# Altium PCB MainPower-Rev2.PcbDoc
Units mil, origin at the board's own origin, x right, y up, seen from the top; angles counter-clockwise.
Board outline 7780 x 7780 mil, 4 copper layers (Top Layer, Internal Plane 1, Internal Plane 2, Bottom Layer); 127 components, 91 nets, 528 pads, 0 vias.
Unrouted connection lines stored in the file: 357.
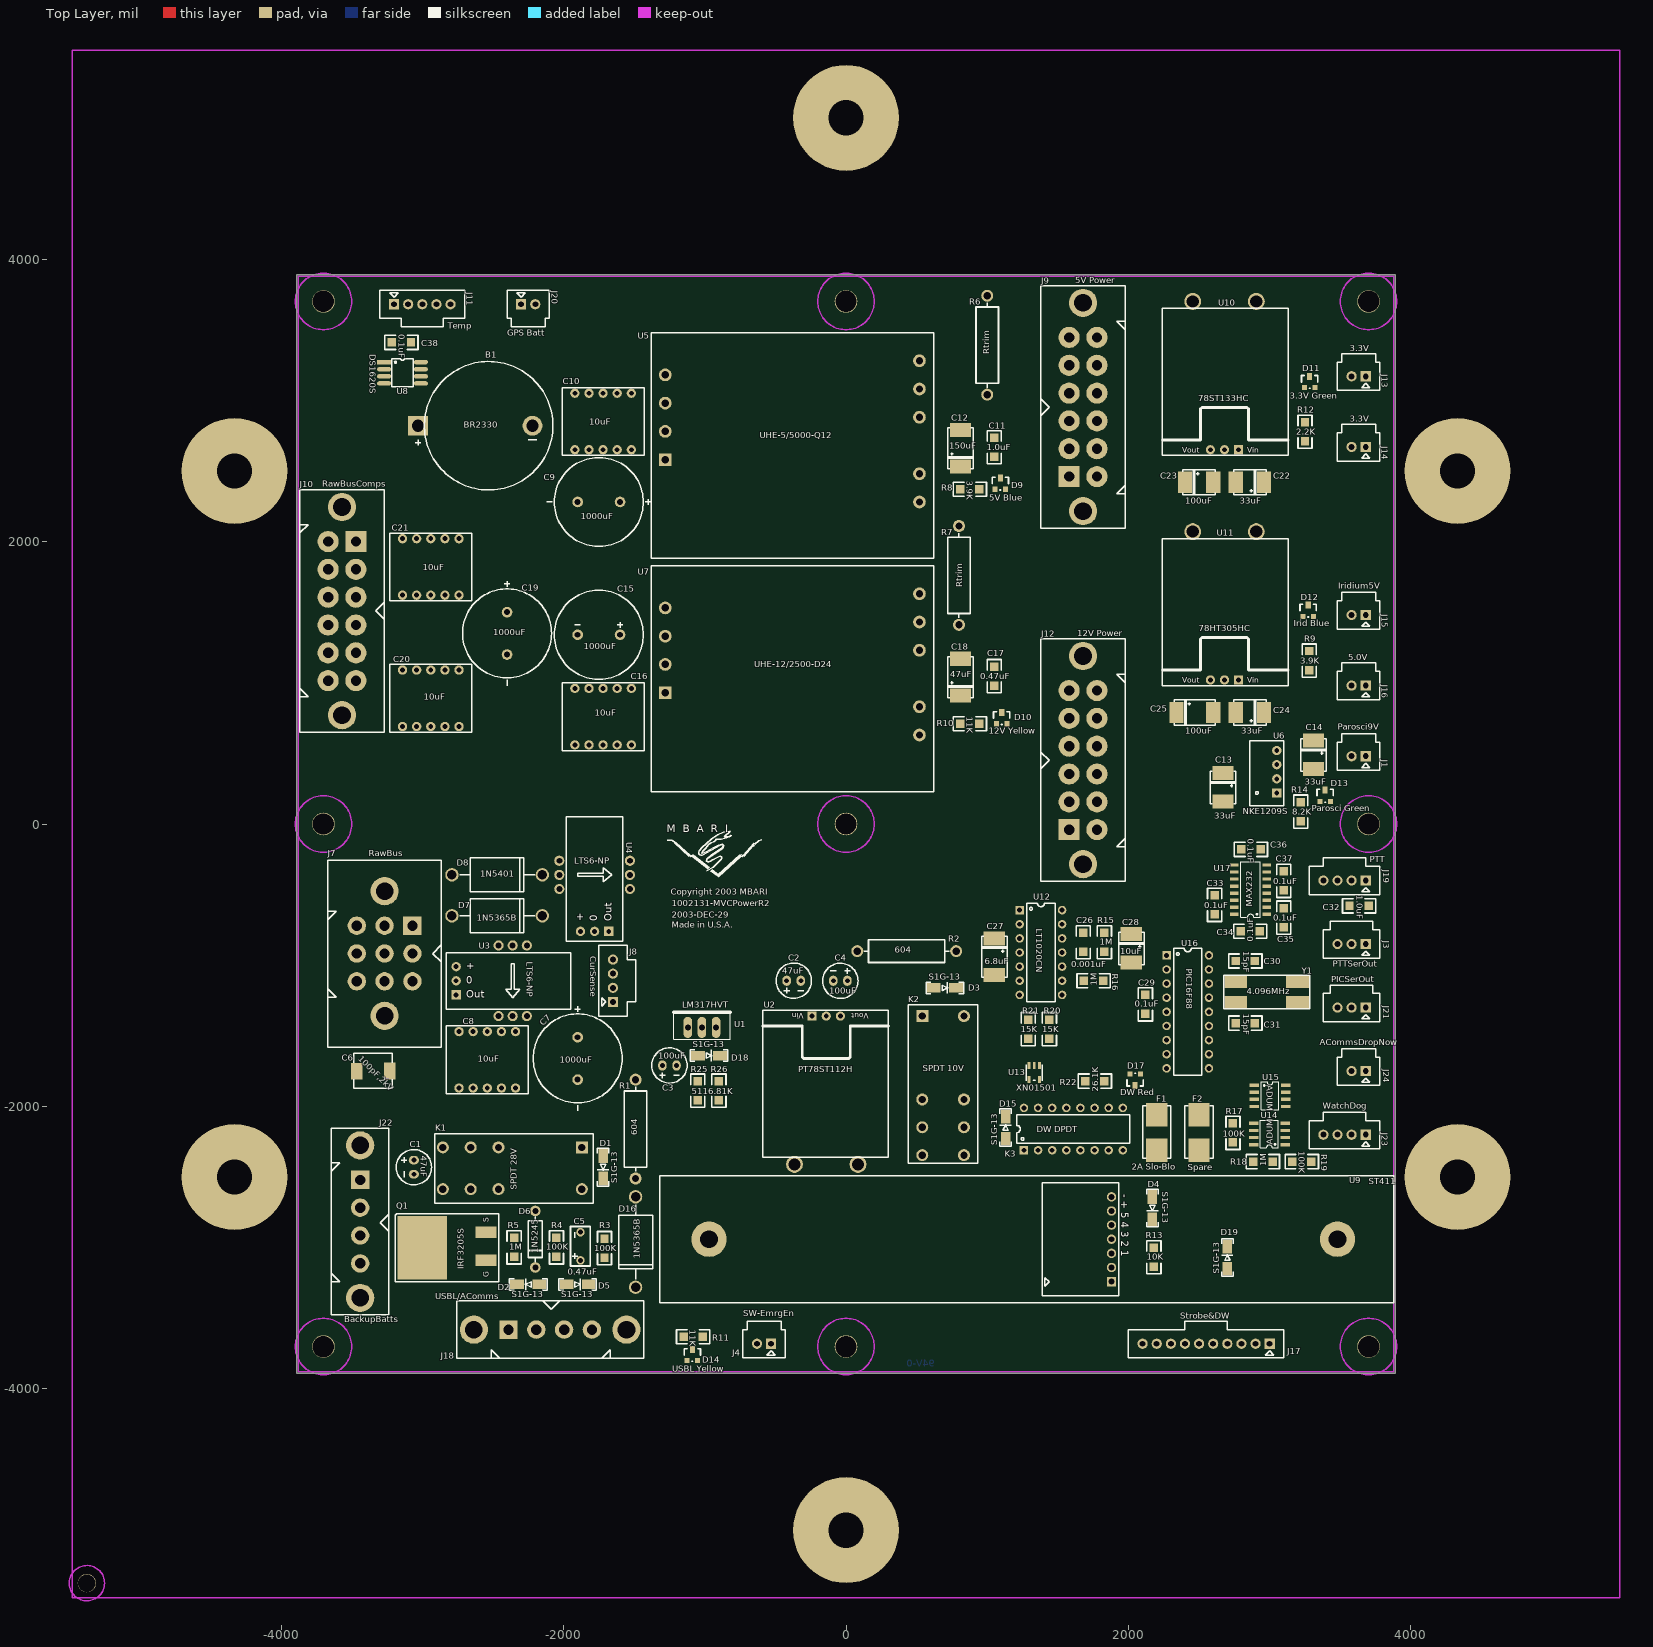
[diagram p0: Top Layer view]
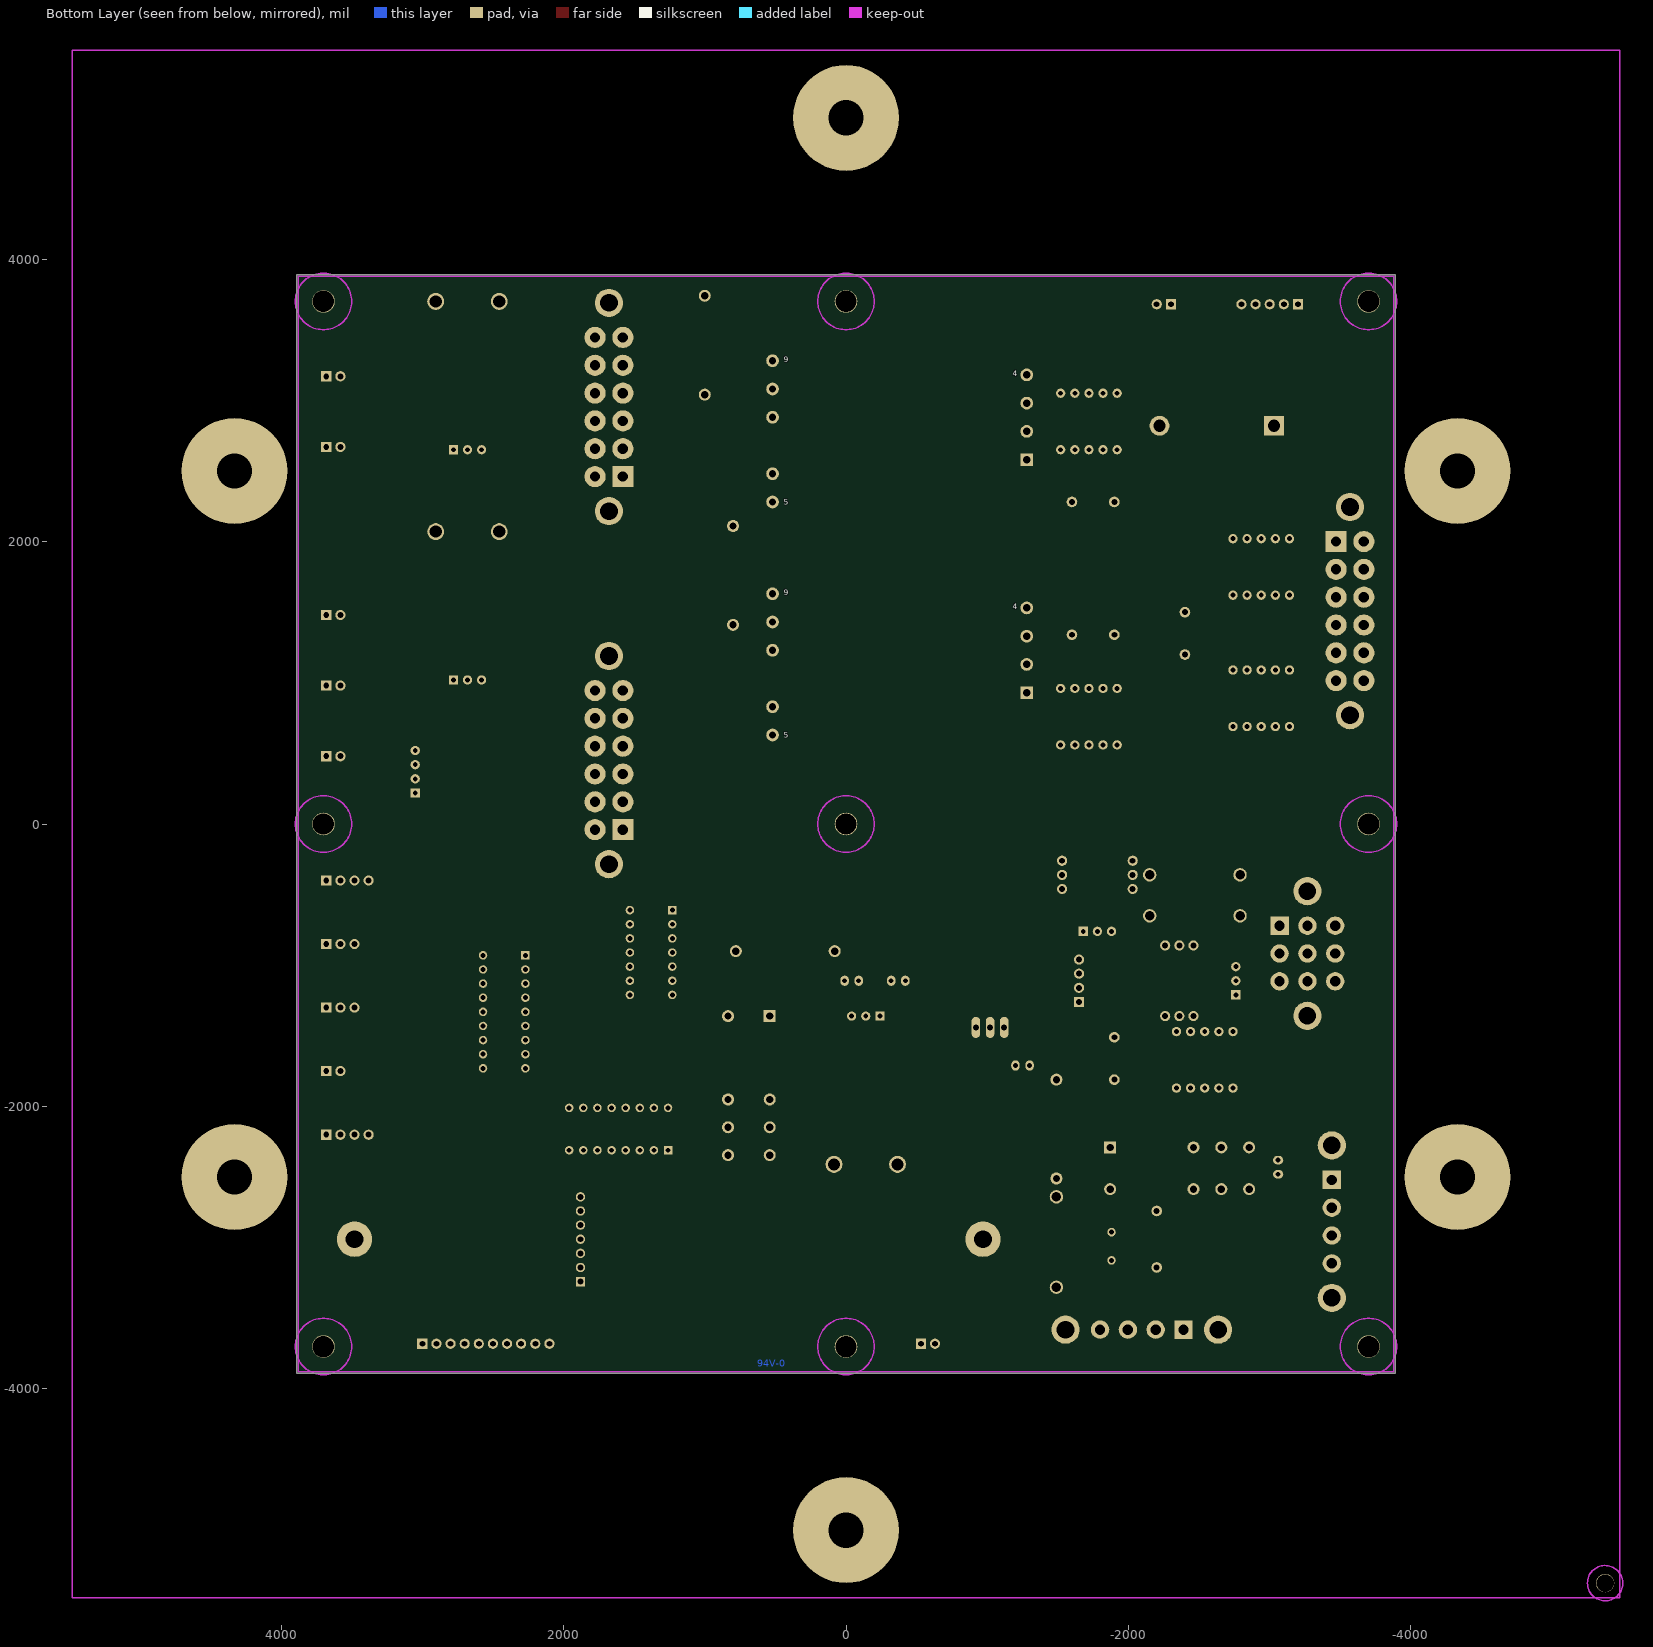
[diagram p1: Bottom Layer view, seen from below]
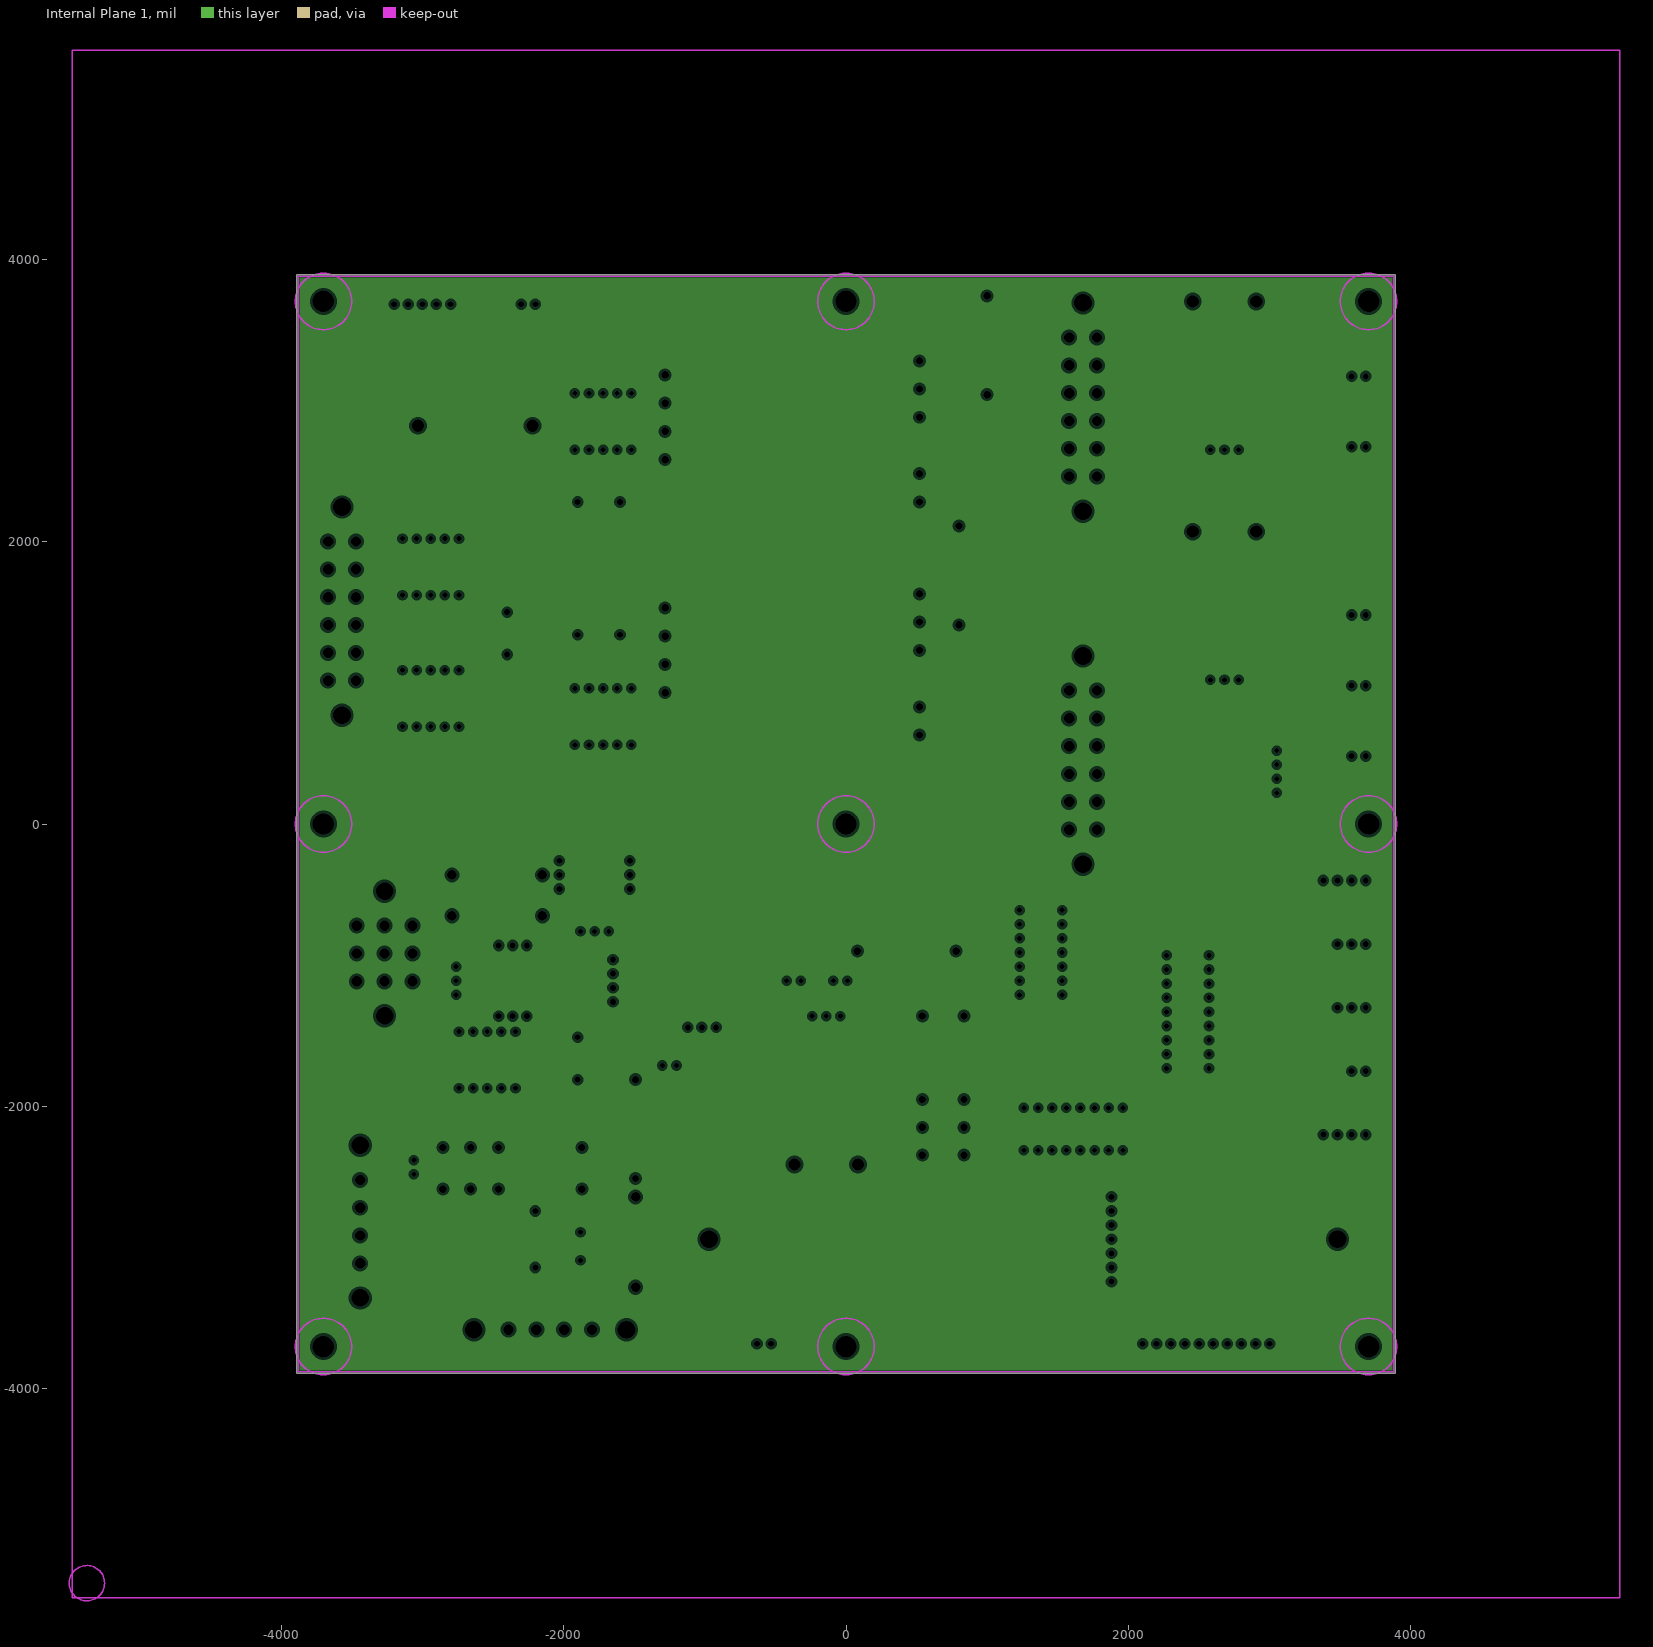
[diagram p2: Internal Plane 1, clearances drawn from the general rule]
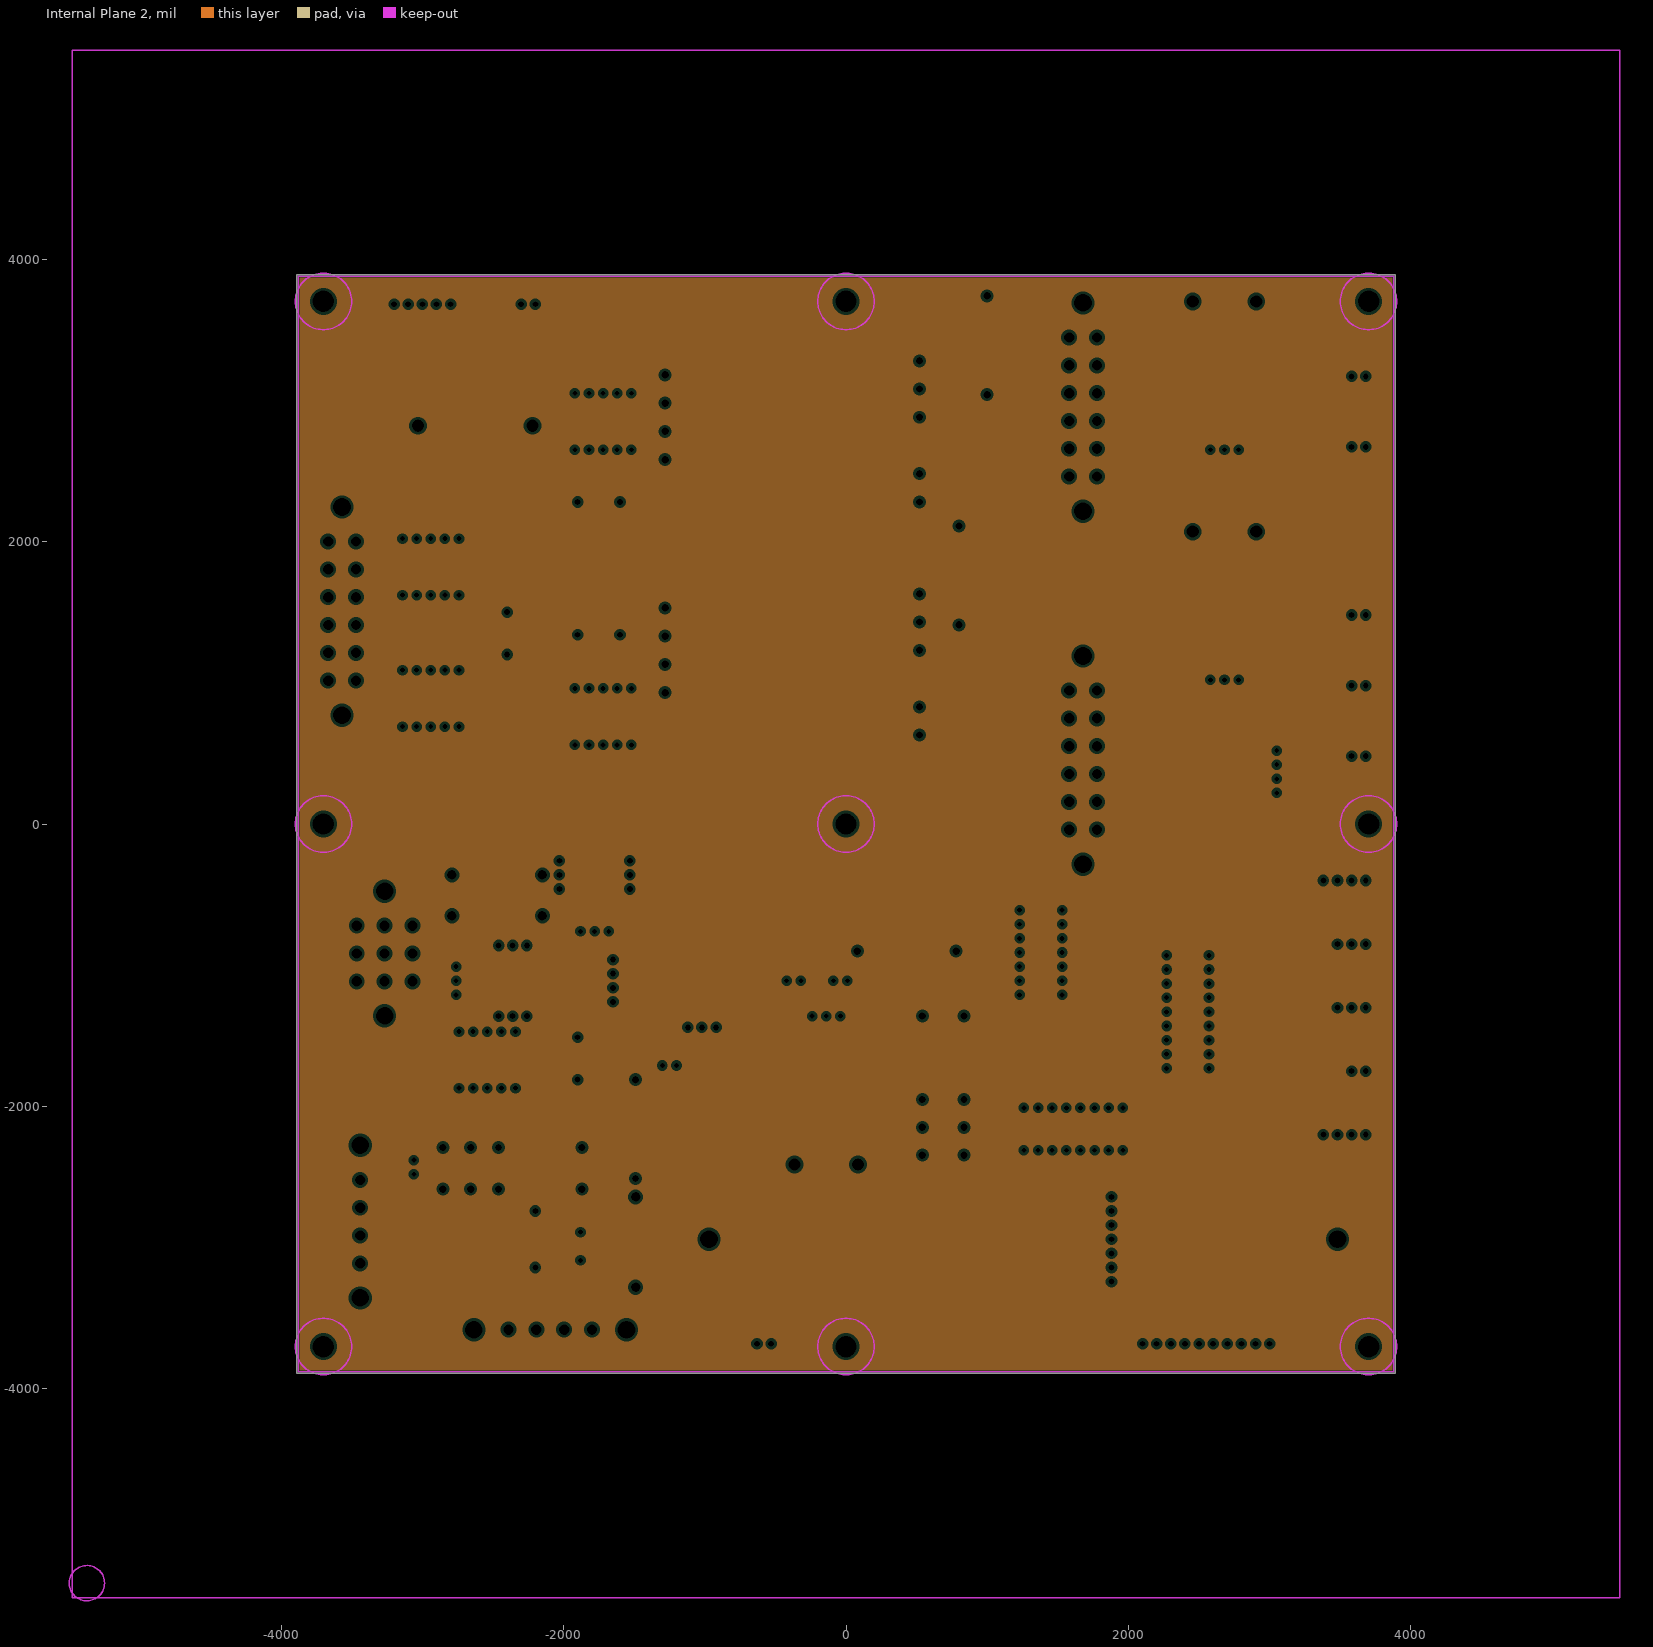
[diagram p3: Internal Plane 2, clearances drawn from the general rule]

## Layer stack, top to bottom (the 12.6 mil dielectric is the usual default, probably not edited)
Top Layer: signal copper 1.4
Dielectric: dielectric 12.6, FR-4, Dk 4.8
Internal Plane 1: plane copper 1.4
Dielectric: dielectric 12.6, FR-4, Dk 4.8
Internal Plane 2: plane copper 1.4
Dielectric: dielectric 12.6, FR-4, Dk 4.8
Bottom Layer: signal copper 1.4

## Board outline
-3890,3890 3890,3890 3890,-3890 -3890,-3890

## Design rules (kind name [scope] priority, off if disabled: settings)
Clearance powers [(InNetClass('BackupBattPower') OR InNetClass('RawPower') OR InNetClass('RegVoltage'))] p1: gap=20
Clearance [All] p2: gap=10
ComponentClearance [All] p1 off: gap=10 collisioncheckmode=0
FanoutControl Fanout_Small [(CompPinCount < 5)] p1: bgadir=Out bgaviamode=Centered fanoutstyle=Auto fanoutdirection=OutThenIn viagrid=1 // Fanout_Small (Default Rule)
FanoutControl Fanout_Default [All] p2: bgadir=Out bgaviamode=Centered fanoutstyle=Auto fanoutdirection=Alternating viagrid=1 // Fanout_Default (Default Rule)
FanoutControl Fanout_BGA [IsBGA] p4: bgadir=Out bgaviamode=Centered fanoutstyle=Auto fanoutdirection=Alternating viagrid=1 // Fanout_BGA (Default Rule)
FanoutControl Fanout_LCC [IsLCC] p5: bgadir=Out bgaviamode=Centered fanoutstyle=Auto fanoutdirection=Alternating viagrid=1 // Fanout_LCC (Default Rule)
HoleSize [All] p1: absolutevalues=TRUE maxlimit=250 minlimit=1 maxpercent=80.000 minpercent=20.000
PlaneClearance [All] p1: clearance=20
PlaneConnect [All] p1: planeconnectstyle=Relief reliefexpansion=20 reliefentries=4 reliefconductorwidth=10 reliefairgap=10
PolygonConnect [All] p1: connectstyle=Relief reliefconductorwidth=10 reliefentries=4 polygonreliefangle="90 Angle"
RoutingCorners [All] p1: cornerstyle=Round minsetback=100 maxsetback=100
RoutingLayers [All] p1: top layer=Horizontal bottom layer=Vertical
RoutingPriority raw_powers [InNetClass('RawPower')] p1: routingpriority=90
RoutingPriority regpow [InNetClass('RegVoltage')] p2: routingpriority=70
RoutingPriority battpow [InNetClass('BackupBattPower')] p3: routingpriority=80
RoutingPriority [All] p4: routingpriority=0
RoutingVias [All] p1: holewidth=35 width=52 viastyle="Through Hole" minholewidth=28 minwidth=35 maxholewidth=86 maxwidth=100
SolderMaskExpansion [All] p1: expansion=4
TestPointUsage [All] p1: valid=0 allowmultiple=FALSE
Testpoint [All] p1: side=15 testpointundercomponent=TRUE minsize=40 maxsize=100 preferedsize=60 minholesize=0 maxholesize=40 preferedholesize=32 testpointgrid=1 style=1023 order=-539222988
Width raw_power [InNetClass('RawPower')] p1: maxlimit=500 minlimit=10 preferedwidth=10 toplayer_minwidth=20 toplayer_prefwidth=50 bottomlayer_minwidth=20 bottomlayer_prefwidth=50 minimp=50.000000 maximp=50.000000 favimp=50.000000
Width backup_batt_pow [InNetClass('BackupBattPower')] p2: maxlimit=500 minlimit=10 preferedwidth=10 toplayer_minwidth=20 toplayer_prefwidth=30 bottomlayer_minwidth=20 bottomlayer_prefwidth=30 minimp=50.000000 maximp=50.000000 favimp=50.000000
Width reg_pow [InNetClass('RegVoltage')] p3: maxlimit=250 minlimit=10 preferedwidth=10 toplayer_minwidth=20 toplayer_prefwidth=30 bottomlayer_minwidth=20 bottomlayer_prefwidth=30 minimp=50.000000 maximp=50.000000 favimp=50.000000
Width [All] p4: maxlimit=500 minlimit=8 preferedwidth=12 toplayer_prefwidth=10 bottomlayer_prefwidth=10 minimp=50.000000 maximp=50.000000 favimp=50.000000
7 further rules are at their usual default settings.

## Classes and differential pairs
component class Watchdog-Rev2: C26 C27 C28 C29 C30 C31 C33 C34 C35 C36 C37 D15 D17 F1 F2 J3 J21 J25 J26 K3 R15 R16 R17 R18 R19 R20 R21 R22 R23 R24 U12 U13 U14 U15 U16 U17 Y1
component class "Parosci Iso": C13 C14 U6
component class MainPower-Rev2: B1 C19 C20 C21 C32 C38 D9 D10 D11 D12 D13 D14 D19 J1 J7 J8 J9 J10 J11 J12 J13 J14 J15 J16 J17 J18 J19 J20 J22 J23 J24 R8 R9 R10 R11 R12 R13 R14 U8 U9
component class Iridium: C24 C25 U11
component class Input-Caps-Diodes-CurrentSensing: C6 C7 C8 D7 D8 U3 U4
component class ISO12V-30W-MVC-Rev2: C15 C16 C17 C18 R7 U7
component class ISO5V-25W-MVC-Rev2: C9 C10 C11 C12 R6 U5
component class GPS: C22 C23 U10
component class BattBacked-Rev2: C1 C2 C3 C4 C5 D1 D2 D3 D4 D5 D6 D16 D18 J4 K1 K2 Q1 R1 R2 R3 R4 R5 R25 R26 U1 U2
net class BackupBattPower: BACKUP10+ BACKUP28+ DW28V DW+ DW- DWGND SW10VDC V+USBL
net class RegVoltage: 12VGND DW5V IRID5V+ MVC3.3V+ MVC5V+ MVC12V+ MVCGND PARO9V+ PARO9VGND SW10VDC V+USBL
net class RawPower: ELEC+ LOCO+ RAWBUS+ RAWBUS-

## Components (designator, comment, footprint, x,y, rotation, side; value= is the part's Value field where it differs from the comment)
B1 "BR2330" BR2330-BAT -2530,2820 r180 top
C1 "47uF" RAD0.1L_0.25D -3060,-2380 r270 top
C2 "47uF" RAD0.1L_0.25D -420,-1110 r0 top
C3 "100uF" RAD0.1L_0.25D -1300,-1710 r0 top
C4 "100uF" RAD0.1L_0.25D 10,-1110 r180 top
C5 "0.47uF" RAD0.2_POL -1880,-3090 r90 top
C6 "100pF,2kV" ECK -3470,-1730 r0 top
C7 "1000uF" RAD0.3L_0.63D -1900,-1510 r270 top
C8 "10uF" CAPSTICK-CS4-5 -2740,-1470 r0 top
C9 "1000uF" RAD0.3L_0.63D -1600,2280 r180 top
C10 "10uF" CAPSTICK-CS4-5 -1520,2650 r180 top
C11 "1.0uF" 1206 1050,2600 r90 top
C12 "150uF" 7343pol 810,2530 r90 top
C13 "33uF" 6032pol 2670,360 r270 top
C14 "33uF" 6032pol 3310,590 r270 top
C15 "1000uF" RAD0.3L_0.63D -1600,1340 r180 top
C16 "10uF" CAPSTICK-CS4-5 -1520,560 r180 top
C17 "0.47uF" 1206 1050,980 r90 top
C18 "47uF" 7343pol 810,910 r90 top
C19 "1000uF" RAD0.3L_0.63D -2400,1500 r270 top
C20 "10uF" CAPSTICK-CS4-5 -2740,690 r180 top
C21 "10uF" CAPSTICK-CS4-5 -3140,2020 r0 top
C22 "33uF" 6032pol 2960,2420 r180 top
C23 "100uF" 6032pol 2400,2420 r0 top
C24 "33uF" 6032pol 2960,790 r180 top
C25 "100uF" 7343pol 2340,790 r0 top
C26 "0.001uF" 1206 1680,-770 r270 top
C27 "6.8uF" 7343pol 1050,-810 r270 top
C28 "10uF" 6032pol 2020,-780 r270 top
C29 "0.1uF" 1206 2120,-1210 r270 top
C30 "15pF" 1206 2760,-970 r0 top
C31 "15pF" 1206 2760,-1410 r0 top
C32 "1.0uF" 1206 3700,-580 r180 top
C33 "0.1uF" 1206 2610,-640 r90 top
C34 "0.1uF" 1206 2930,-760 r180 top
C35 "0.1uF" 1206 3100,-730 r90 top
C36 "0.1uF" 1206 2800,-180 r0 top
C37 "0.1uF" 1206 3100,-470 r90 top
C38 "0.1uF" 1206 -3080,3410 r180 top
D1 "S1G-13" SMA -1720,-2430 r270 top
D2 "S1G-13" SMA -2250,-3260 r180 top
D3 "S1G-13" SMA 700,-1160 r0 top
D4 "S1G-13" SMA 2170,-2720 r270 top
D5 "S1G-13" SMA -1900,-3260 r0 top
D6 "1N5245" DIODE0.4 -2200,-2740 r270 top
D7 "1N5365B" DO-201AD -2790,-650 r0 top
D8 "1N5401" DO-201AD -2790,-360 r0 top
D9 "5V Blue" SOT-23 1130,2370 r0 top
D10 "12V Yellow" SOT-23 1140,710 r0 top
D11 "3.3V Green" SOT-23 3320,3090 r0 top
D12 "Irid Blue" SOT-23 3310,1470 r0 top
D13 "Parosci Green" SOT-23 3430,160 r0 top
D14 "USBL Yellow" SOT-23 -1050,-3800 r0 top
D15 "S1G-13" SMA 1130,-2150 r90 top
D16 "1N5365B" DO-201AD -1490,-2640 r270 top
D17 "DW Red" SOT-23 2010,-1770 r180 top
D18 "S1G-13" SMA -970,-1640 r0 top
D19 "S1G-13" SMA 2700,-3070 r90 top
F1 "2A Slo-Blo" SMF-OMNIBLOK 2200,-2310 r90 top
F2 "Spare 2A Slo-Blo" SMF-OMNIBLOK 2500,-2310 r90 top
J1 "Parosci9V" CGRID2 3680,480 r0 top
J3 "PTTSerOut" CGRID3 3680,-850 r0 top
J4 "SW-EmrgEn" CGRID2 -530,-3680 r0 top
J7 "RawBus" PLC09 -3070,-720 r270 top
J8 "CurSense" CGRID4 -1650,-1260 r270 top
J9 "5V Power" PLB12 1580,2460 r90 top
J10 "RawBusComps" PLB12 -3470,2000 r270 top
J11 "Temp" CGRID5 -3200,3680 r180 top
J12 "12V Power" PLB12 1580,-40 r90 top
J13 "3.3V" CGRID2 3680,3170 r0 top
J14 "3.3V" CGRID2 3680,2670 r0 top
J15 "Iridium5V" CGRID2 3680,1480 r0 top
J16 "5.0V" CGRID2 3680,980 r0 top
J17 "Strobe&DW" CGRID10 3000,-3680 r0 top
J18 "USBL/AComms" PLA04 -2390,-3580 r0 top
J19 "PTT" CGRID4 3680,-400 r0 top
J20 "GPS Batt" CGRID2 -2300,3680 r180 top
J21 "PICSerOut" CGRID3 3680,-1300 r0 top
J22 "BackupBatts" PLA04 -3440,-2520 r270 top
J23 "WatchDog" CGRID4 3680,-2200 r0 top
J24 "ACommsDropNow" CGRID2 3680,-1750 r0 top
K1 "SPDT 28V" NAIS-LZ -1870,-2290 r180 top
K2 "SPDT 10V" NAIS-LZ 540,-1360 r270 top
K3 "DW DPDT" DIP16 1260,-2310 r90 top
Q1 "IRF3205S" D2PAK -2550,-3090 r90 top
R1 "604" AXIAL0.7 -1490,-2510 r90 top
R2 "604" AXIAL0.7 780,-900 r180 top
R3 "100K" 1206 -1710,-3070 r90 top
R4 "100K" 1206 -2050,-2930 r270 top
R5 "1M" 1206 -2350,-2930 r270 top
R6 "Rtrim" AXIAL0.7 1000,3740 r270 top
R7 "Rtrim" AXIAL0.7 800,2110 r270 top
R8 "3.9K" 1206 810,2370 r0 top
R9 "3.9K" 1206 3280,1090 r90 top
R10 "11K" 1206 810,710 r0 top
R11 "11K" 1206 -1150,-3630 r0 top
R12 "2.2K" 1206 3250,2710 r90 top
R13 "10K" 1206 2180,-3000 r270 top
R14 "8.2K" 1206 3220,20 r90 top
R15 "1M" 1206 1830,-770 r270 top
R16 "1M" 1206 1820,-1110 r180 top
R17 "100K" 1206 2740,-2120 r270 top
R18 "1M" 1206 3020,-2390 r180 top
R19 "100K" 1206 3160,-2390 r0 top
R20 "15K" 1206 1440,-1520 r90 top
R21 "15K" 1206 1290,-1520 r90 top
R22 "26.1K" 1206 1830,-1820 r180 top
R25 "511" 1206 -1050,-1820 r270 top
R26 "6.81K" 1206 -900,-1820 r270 top
U1 "LM317HVT" TO-220 -1120,-1440 r0 top
U2 "PT78ST112H" PT78ST-HORIZ -140,-1360 r180 top
U3 "LTS6-NP" LTS6-NP -2830,-910 r0 top
U4 "LTS6-NP" LTS6-NP -1980,-830 r90 top
U5 "UHE-5/5000-Q12" DATEL-UHE -1280,2580 r0 top
U6 "NKE1209S" NKEDCDC 3050,220 r180 top
U7 "UHE-12/2500-D24" DATEL-UHE -1280,930 r0 top
U8 "DS1620S" SOIC-8 -3270,3270 r0 top
U9 "ST411" ST411 3880,-2940 r270 top locked
U10 "78ST133HC" PT78ST-HORIZ 2680,2650 r0 top
U11 "78HT305HC" PT78ST-HORIZ 2680,1020 r0 top
U12 "LT1020CN" DIP14 1230,-610 r0 top
U13 "XN01501" SC-74A 1370,-1810 r0 top
U14 "ADUM1100AR" SO-G8/D5 3110,-2270 r90 top
U15 "ADUM1100AR" SO-G8/D5 2890,-1850 r270 top
U16 "PIC16F88" DIP18 2270,-930 r0 top
U17 "MAX232" SOIC-16-0.15W 2980,-640 r90 top
Y1 "4.096MHz" MA-506 2760,-1260 r0 top

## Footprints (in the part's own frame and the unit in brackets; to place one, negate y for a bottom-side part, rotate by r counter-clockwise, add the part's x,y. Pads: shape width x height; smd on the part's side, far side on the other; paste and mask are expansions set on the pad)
1206 [mil]
  rect 60x60 smd: 1(0,0) 2(135,0)
  silkscreen extent -50,-50 185,50
6032pol [mil]
  rect 100x150 smd: 1(0,0) 2(200,0)
  silkscreen extent -15,-90 215,90
7343pol [mil]
  rect 100x150 smd: 1(0,0) 2(260,0)
  silkscreen extent -15,-90 275,90
AXIAL0.7 [mil]
  round 85 hole 52: 1(0,0) 2(700,0)
  silkscreen extent 50,-80 650,80
BR2330-BAT [mil] "BR2330 lithium battery horiz mounted"
  rect 140x140 hole 86: 1(500,0)
  round 140 hole 86: 2(-310,0)
  silkscreen extent -455,-455 520,455
CAPSTICK-CS4-5 [mil]
  round 66 hole 35: 1(0,0) 1(100,0) 1(200,0) 1(300,0) 1(400,0) 2(0,-400) 2(100,-400) 2(200,-400) 2(300,-400) 2(400,-400)
  silkscreen extent -90,-440 490,40
CGRID2 [mil]
  rect 72x72 hole 42: 1(0,0)
  round 72 hole 42: 2(-100,0)
  silkscreen extent -200,-100 100,160
CGRID3 [mil]
  rect 72x72 hole 42: 1(0,0)
  round 72 hole 42: 2(-100,0) 3(-200,0)
  silkscreen extent -300,-100 100,160
CGRID4 [mil]
  rect 72x72 hole 42: 1(0,0)
  round 72 hole 42: 2(-100,0) 3(-200,0) 4(-300,0)
  silkscreen extent -400,-100 100,160
CGRID5 [mil]
  rect 72x72 hole 42: 1(0,0)
  round 72 hole 42: 2(-100,0) 3(-200,0) 4(-300,0) 5(-400,0)
  silkscreen extent -500,-100 100,160
CGRID10 [mil] "10 pin Molex CGRID-SL straight"
  rect 72x72 hole 42: 1(0,0)
  round 72 hole 42: 2(-100,0) 3(-200,0) 4(-300,0) 5(-400,0) 6(-500,0) 7(-600,0) 8(-700,0) 9(-800,0) 10(-900,0)
  silkscreen extent -1000,-100 100,160
D2PAK [mil] "IRF D2Pak SMD-220"
  rect 82x150 smd: 1(0,0) 3(200,0)
  rect 450x350 smd: 2(90,450)
  silkscreen extent -150,-90 330,640
DATEL-UHE [mil] "Datel UHE 1.6x2.0 DC/DC Converter"
  rect 90x90 hole 52: 1(0,0)
  round 90 hole 52: 2(0,200) 3(0,400) 4(0,600) 5(1800,-300) 6(1800,-100) 7(1800,300) 8(1800,500) 9(1800,700)
  silkscreen extent -100,-700 1900,900
DIODE0.4 [mil]
  round 75 hole 42: 1(0,0) 2(400,0)
  silkscreen extent 40,-50 360,50
DIP14 [mil]
  rect 60x60 hole 35: 1(0,0)
  round 60 hole 35: 2(0,-100) 3(0,-200) 4(0,-300) 5(0,-400) 6(0,-500) 7(0,-600) 8(300,-600) 9(300,-500) 10(300,-400) 11(300,-300) 12(300,-200) 13(300,-100) 14(300,0)
  silkscreen extent 50,-650 250,50
DIP16 [mil]
  rect 60x60 hole 35: 1(0,0)
  round 60 hole 35: 2(0,-100) 3(0,-200) 4(0,-300) 5(0,-400) 6(0,-500) 7(0,-600) 8(0,-700) 9(300,-700) 10(300,-600) 11(300,-500) 12(300,-400) 13(300,-300) 14(300,-200) 15(300,-100) 16(300,0)
  silkscreen extent 50,-750 250,50
DIP18 [mil]
  rect 60x60 hole 35: 1(0,0)
  round 60 hole 35: 2(0,-100) 3(0,-200) 4(0,-300) 5(0,-400) 6(0,-500) 7(0,-600) 8(0,-700) 9(0,-800) 10(300,-800) 11(300,-700) 12(300,-600) 13(300,-500) 14(300,-400) 15(300,-300) 16(300,-200) 17(300,-100) 18(300,0)
  silkscreen extent 50,-850 250,50
DO-201AD [mil]
  round 95 hole 67: 1(0,0) 2(640,0)
  silkscreen extent 55,-120 585,120
ECK [mm]
  rect 2x3 smd: 1(0.15,-0.5) 2(6.075,-0.475)
  silkscreen extent -0.4,-3.6 6.5,2.7
LTS6-NP [mil]
  round 72 hole 42: 1(370,-450) 2(470,-450) 3(570,-450) 4(570,50) 5(470,50) 6(370,50)
  rect 66x66 hole 35: a(70,-300)
  round 66 hole 35: b(70,-200) c(70,-100)
  silkscreen extent 0,-400 880,0
MA-506 [mm] "Epson Quartz Crystal"
  rect 4.1x2.1 smd: 1(0,0) 2(11.1,0) 3(11.1,3.6) 4(0,3.6)
  silkscreen extent -2.2,-1.2 13.3,4.8
NAIS-LZ [mil] "NAIS LZ Relay"
  rect 85x85 hole 52: 1(0,0)
  round 85 hole 52: 2(590.55,0) 3(787.4,0) 4(984.25,0) 5(984.25,295.28) 6(787.4,295.28) 7(590.55,295.28) 8(0,295.28)
  silkscreen extent -79,-98 1043,394
NKEDCDC [mil]
  rect 66x66 hole 35: 1(0,0)
  round 66 hole 35: 2(0,-100) 3(0,-200) 4(0,-300)
  silkscreen extent -50,-370 190,90
PLA04 [mil] "Positronic 1x4 pin"
  round 200 hole 125: 0(-244.5,0) 0(835.5,0)
  rect 130x130 hole 73: 1(0,0)
  round 130 hole 73: 2(197,0) 3(394,0) 4(591,0)
  silkscreen extent -366,-204 956,204
PLB12 [mil] "Positronic 2x6 pin"
  round 200 hole 125: 0(-244.5,-98.5) 0(1229.5,-98.5)
  rect 150x150 hole 73: 1(0,0)
  round 150 hole 73: 2(197,0) 3(394,0) 4(591,0) 5(788,0) 6(985,0) 7(0,-197) 8(197,-197) 9(394,-197) 10(591,-197) 11(788,-197) 12(985,-197)
  silkscreen extent -366,-398 1350,202
PLC09 [mil] "Positronic 3x3 pins"
  round 200 hole 125: 0(-244.5,-197) 0(638.5,-197)
  rect 130x130 hole 73: 1(0,0)
  round 130 hole 73: 2(197,0) 3(394,0) 4(0,-197) 5(197,-197) 6(394,-197) 7(0,-394) 8(197,-394) 9(394,-394)
  silkscreen extent -465,-598 859,205
PT78ST-HORIZ [mil]
  round 120 hole 86: 0(-225,1050) 0(225,1050)
  rect 65x65 hole 35: 1(100,0)
  round 65 hole 35: 2(0,0) 3(-100,0)
  silkscreen extent -440,-40 450,1000
RAD0.1L_0.25D [mil]
  oval 60x72 hole 35: 1(0,0) 2(100,0)
  silkscreen extent -75,-124 175,125
RAD0.2_POL [mil] "Polarized Cap"
  round 60 hole 35: 1(0,0) 2(200,0)
  silkscreen extent -40,-70 240,70
RAD0.3L_0.63D [mil]
  round 75 hole 42: 1(0,0) 2(300,0)
  silkscreen extent -220,-315 520,315
SC-74A [mil] "Mini5 - G1 Panasonic"
  rect 20x50 smd: 1(0,0) 2(-75,0) 3(-75,100) 4(-37,100) 5(0,100)
  silkscreen extent -95,-8 19,106
SMA [mm] "SMA Diode"
  rect 2.5x1.7 smd: 1(-2,0) 2(2,0)
  silkscreen extent -3.38,-1.02 3.38,1.02
SMF-OMNIBLOK [mil] "SMD Nano Fuse Holder"
  rect 167x150 smd: 1(0,0) 2(250,0)
  silkscreen extent -55,-100 315,100
SO-G8/D5 [mm]
  rect 0.6x1.7 smd: 1(0,0) 2(1.27,0) 3(2.54,0) 4(3.81,0) 5(3.81,5.7) 6(2.54,5.7) 7(1.27,5.7) 8(0,5.7)
  silkscreen extent -0.59,1.25 4.41,4.45
SOIC-8 [mil]
  rect 100x30 smd: 1(0,0)
  oval 100x30 smd: 2(0,-50) 3(0,-100) 4(0,-150) 5(260,-150) 6(260,-100) 7(260,-50) 8(260,0)
  silkscreen extent 55,-175 205,25
SOIC-16-0.15W [mm] "SOIC-16 0.15\"Wide 1.27mm Pitch"
  rect 0.6x1.55 smd: 1(0,0) 2(1.27,0) 3(2.54,0) 4(3.81,0) 5(5.08,0) 6(6.35,0) 7(7.62,0) 8(8.89,0) 9(8.89,5.85) 10(7.62,5.85) 11(6.35,5.85) 12(5.08,5.85) 13(3.81,5.85) 14(2.54,5.85) 15(1.27,5.85) 16(0,5.85)
  silkscreen extent -0.55,1.18 9.44,4.67
SOT-23 [mil]
  rect 36x36 smd: 1(0,0) 2(-75,0)
  rect 36x50 smd: 3(-37,80)
  silkscreen extent -95,-5 20,85
ST411 [mil]
  round 250 hole 125: 00(0,-400) 0(0,-4850)
  rect 66x66 hole 42: 1(300,-2000)
  round 66 hole 42: 2(200,-2000) 3(100,-2000) 4(0,-2000) 5(-100,-2000) 6(-200,-2000) 7(-300,-2000)
  silkscreen extent -450,-5200 450,0
TO-220 [mil]
  oval 60x150 hole 42: 1(0,0) 2(100,0) 3(200,0)
  silkscreen extent -100,-85 300,108

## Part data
B1: library part Battery, "Multicell Battery"
C1 C2 C3 C4 C5 C7 C9 C13 C14 C15 C19 C22 C23 C24 C25 C27 C28: library part "CAPACITOR POL", "Capacitor"
C6 C8 C10 C11 C16 C17 C20 C21 C26 C29 C30 C31 C32 C33 C34 C35 C36 C37 C38: library part CAPACITOR, "Capacitor"
C12 C18: library part "CAPACITOR POL", "Tantalum Capacitor"
D1 D2 D3 D4 D5 D8 D15 D18 D19: library part DIODE_S, "Diode"
D6 D7 D16: library part ZENER3, "Zener Diode"
D9 D10 D11 D12 D13 D14 D17: library part LED, "LED"
F1 F2: library part "Fuse 2", "Fuse"
J1 J4 J19 J20: library part CON2, "Connector"
J3 J21: library part CON3, "Connector"
J7: library part CON3X3-PLC, "Positronic 9 pin connector"
J8: library part CON4, "Connector"
J9 J10 J12: library part CON12-PLB-2, "Positronic 12 pin connector"
J11: library part CON5, "Connector"
J13 J14 J15 J16 J24: library part CON2, "Connector C-Grid"
J17: library part CON10, "Connector"
J18 J22: library part CON4-PLA, "Positronic 4 pin connector"
J23: library part CON4, "Connector C-Grid"
K1 K2: library part RELAY-NAIS-LZ-SPDT, "Nais LZ Relay SPDT"
K3: library part RELAY-PB-V23105, "P&B V23105 Relay DPDT"
Q1: library part HEXFET-N, "HexFET"
R1 R2 R3 R4 R5 R6 R7 R8 R9 R10 R11 R12 R13 R14 R15 R16 R17 R18 R19 R20 R21 R22 R25 R26: library part RESISTOR, "Resistor"
U1: "Regulator"
U2 U10: library part PT78STXXX, "Power Trends Switching Reg"
U3 U4: "Current Transducer"
U5 U7: library part UHE, "Datel UHE DC->DC Isolated Converter"
U6: "DC->DC Isol Converter 12->9VDC"
U8: library part DS1620, "DallasSemi Digital Thermometer and Thermostat"
U9: "Novatech Strobe Beacon"
U11: library part PT78STXXX, "Power Trends Switching Reg 5V, 3A"
U12: library part LT1020, "Micropower Regulator"
U13: "Dual NPN Common Emitter Transistor"
U14 U15: "Digital Isolator"
U16: "PIC16F88 microcontroller DIP,SOIC package"
U17: "MAX232 Communications Chip"
Y1: library part XTAL, "Crystal Oscillator"

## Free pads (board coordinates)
  round 130 hole 125: 0(-5375,-5375)
  round 160 hole 152: 0(-3700,-3700) 1(-3700,0) 1(0,-3700) 1(0,0) 1(0,3700) 1(3700,-3700) 1(3700,0) 2(3700,3700) 3(-3700,3700)
  round 750 hole 250: 0(0,5000) 1(0,-5000) 2(-4330,-2500) 2(-4330,2500) 3(4330,-2500) 3(4330,2500)

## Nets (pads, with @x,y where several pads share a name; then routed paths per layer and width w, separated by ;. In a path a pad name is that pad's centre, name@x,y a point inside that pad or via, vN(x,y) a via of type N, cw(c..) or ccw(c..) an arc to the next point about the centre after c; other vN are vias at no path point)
12VGND: C24.2 C25.2 D12.3 J15.2 J16.2 U11.2
12VGND: C22.2 C23.2 D11.3 J13.2 J14.2 U10.2
AN0V: J8.4 U3.b U4.b
AN5V: J8.1 U3.c U4.c
BACKUP10+: J22.3 K2.2
BACKUP28+: J22.1 K1.2
DROPNOW: J24.1 R18.1 R21.2 U16.1
DW5V: C26.1 C28.1 C29.1 R15.1 U12.2 U14.8 U15.1 U15.3 U16.4 U16.14
DW28V: C27.1 D2.2 D15.2 D16.2 D18.2 J4.2 J18.1 K1.3 K3.8 K3.16 R11.1 U1.3 U12.3
DW+: F1.2 J17.2 J17.3
DW-: D17.3 J17.1 K3.13
DWGND: C3.2 C27.2 C28.2 C29.2 C30.2 C31.2 D2.1 D14.3 D16.1 J3.3 J18.2 J18.4 J21.3 J24.2 K3.9 Q1.2 R16.2 R17.2 R18.2 R26.1 U12.9 U13.4 U14.5 U14.7 U15.4 U16.5
ELEC+: C1.1 C2.1 C9.1 C10.1 C15.1 C16.1 C19.1 C20.1 C21.1 J10.1 J10.2 J10.3 J10.4 J10.5 J10.6 K1.4 R1.2 R2.2 U2.1 U4.1 U4.2 U4.3 U5.1 U7.1
ELECCUR: J8.3 U4.a
IRID5V+: C25.1 J15.1 J16.1 R9.1 U11.3
ISO5VSENSE+: J9.3 U5.5
ISO5VSENSE-: J9.9 R6.2 U5.8
LOCO+: C7.1 C8.1 J7.3 U3.1 U3.2 U3.3
LOCOCUR: J8.2 U3.a
MVC3.3V+: C23.1 J13.1 J14.1 R12.1 U10.3
MVC5V+: C11.1 C12.1 J9.1 J9.2 J9.4 J9.5 J9.6 J23.1 R8.1 U5.6 U14.1 U14.3 U15.8
MVC12V+: C13.1 C17.1 C18.1 C22.1 C24.1 J12.1 J12.2 J12.3 J12.4 J12.5 J12.6 R10.1 U6.2 U7.5 U7.6 U10.1 U11.1
MVCGND: C11.2 C12.2 C13.2 C17.2 C18.2 D9.3 D10.3 J9.7 J9.8 J9.10 J9.11 J9.12 J12.7 J12.8 J12.9 J12.10 J12.11 J12.12 J23.3 R7.2 R19.2 U5.7 U6.1 U7.7 U7.8 U14.4 U15.5 U15.7
NetB1_1: B1.1 J20.1
NetB1_2: B1.2 J20.2
NetC4_1: C4.1 K2.4 U2.3
NetC5_1: C5.1 R3.2 R4.1
NetC26_2: C26.2 R15.2 R16.1 U12.11
NetC30_1: C30.1 U16.16 Y1.4
NetC31_1: C31.1 U16.15 Y1.1
NetC32_1: C32.1 D19.2 J19.1
NetC33_1: C33.1 C34.2 U17.16
NetC33_2: C33.2 C36.1 U17.15
NetC34_1: C34.1 U17.2
NetC35_1: C35.1 U17.1
NetC35_2: C35.2 U17.3
NetC36_2: C36.2 U17.6
NetC37_1: C37.1 U17.4
NetC37_2: C37.2 U17.5
NetC38_1: C38.1 J11.2 U8.8
NetC38_2: C38.2 J11.1 U8.4
NetD1_2: D1.2 K1.8 R1.1
NetD3_2: D3.2 K2.8 R2.1
NetD5_2: D5.2 J4.1 R3.1
NetD9_2: D9.2 R8.2
NetD10_2: D10.2 R10.2
NetD11_2: D11.2 R12.2
NetD12_2: D12.2 R9.2
NetD13_2: D13.2 R14.2
NetD14_2: D14.2 R11.2
NetD15_1: D15.1 K3.1 U13.1 U13.2
NetD17_2: D17.2 R22.1
NetD19_1: D19.1 J17.4 U9.00 U9.6
NetF1_1: F1.1 K3.4 R22.2
NetJ3_1: J3.1 U17.14
NetJ3_2: J3.2 U17.13
NetJ5_1: 
NetJ5_2: 
NetJ11_3: J11.3 U8.1
NetJ11_4: J11.4 U8.2
NetJ11_5: J11.5 U8.3
NetJ17_6: J17.6 U9.5
NetJ17_7: J17.7 R13.1 U9.4
NetJ17_8: J17.8 U9.0 U9.3
NetJ17_9: J17.9 R13.2 U9.2
NetJ17_10: J17.10 U9.1
NetJ21_1: J21.1 U17.7
NetJ21_2: J21.2 U17.8
NetJ21_3: 
NetR6_1: R6.1 U5.9
NetR7_1: R7.1 U7.9
NetR17_1: R17.1 U14.6 U16.6
NetR20_1: R20.1 U13.5
NetR20_2: R20.2 U16.17
NetR21_1: R21.1 U13.3
NetR25_2: R25.2 R26.2 U1.1
NetU15_2: U15.2 U16.18
PARO9V+: C14.1 J1.1 R14.1 U6.4
PARO9VGND: C14.2 D13.3 J1.2 U6.3
PICRX: U16.8 U17.9
PICTX: U16.11 U17.10
PTT-TTL-SER-RX: U17.12
PTT-TTL-SER-TX: U17.11
Q1G: D5.1 D6.2 Q1.1 R4.2 R5.2
RAWBUS+: D7.2 D8.2 J7.1 J7.2 J10.0@-3568.5,2244.5 U3.4 U3.5 U3.6 U4.4 U4.5 U4.6
RAWBUS-: C1.2 C2.2 C4.2 C5.2 C6.2 C7.2 C8.2 C9.2 C10.2 C15.2 C16.2 C19.2 C20.2 C21.2 C32.2 D1.1 D3.1 D4.1 D6.1 D7.1 D8.1 J7.0 J7.4 J7.5 J7.6 J10.0@-3568.5,770.5 J10.7 J10.8 J10.9 J10.10 J10.11 J10.12 J19.2 J22.2 J22.4 K1.1 K2.1 Q1.3 R5.1 U2.2 U5.2 U7.2 U9.7
SHIELD: C6.1 J7.7 J7.8 J7.9
SW10VDC: D4.2 J17.5 K2.3
V+USBL: C3.1 D18.1 J18.3 R25.1 U1.2
WDC: J23.2 R19.1 U14.2
WDSTATUS: J23.4 U15.6
pads on no net: D9.1 D10.1 D11.1 D12.1 D13.1 D14.1 D17.1 F2.1 F2.2 J9.0 J12.0 J18.0 J19.3 J19.4 J22.0 K1.5 K1.6 K1.7 K2.5 K2.6 K2.7 K3.2 K3.3 K3.5 K3.6 K3.7 K3.10 K3.11 K3.12 K3.14 K3.15 U2.0 U5.3 U5.4 U7.3 U7.4 U8.5 U8.6 U8.7 U10.0 U11.0 U12.1 U12.4 U12.5 U12.6 U12.7 U12.8 U12.10 U12.12 U12.13 U12.14 U16.2 U16.3 U16.7 U16.9 U16.10 U16.12 U16.13 Y1.2 Y1.3

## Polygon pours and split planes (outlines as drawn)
no net on Internal Plane 1 (split plane): -3869.99,-3869.99 -3869.99,3869.99 3869.99,3869.99 3869.99,-3869.99
no net on Internal Plane 2 (split plane): -3869.99,-3869.99 -3869.99,3869.99 3869.99,3869.99 3869.99,-3869.99

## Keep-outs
Keep-Out Layer:
  circle w10: c-5375,-5375 r125
  circle w10: c-3700,-3700 r200
  circle w10: c0,-3700 r200
  circle w10: c3700,-3700 r200
  circle w10: c3700,0 r200
  circle w10: c0,0 r200
  circle w10: c-3700,0 r200
  circle w10: c-3700,3700 r200
  circle w10: c0,3700 r200
  circle w10: c3700,3700 r200
  lines w10: -5480,-5480 -5480,5480 5480,5480 5480,-5480 -5480,-5480 ; -3880,-3880 -3880,3880 3880,3880 3880,-3880 -3880,-3880
  text ".GKO" at 12740,-6040 h90

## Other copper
Top Layer:
  text ".GTL" at 12740,-6040 h90
Bottom Layer:
  text "94V-0" at 627.07,-3841.21 h50
  text ".GBL" at 12740,-6040 h90

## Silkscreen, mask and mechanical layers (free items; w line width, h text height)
Top Overlay:
  lines w10: -1267,-114 -1235,-116 -1204,-134 -1103,-225 -1090,-221 -1083,-222 -969,-309 ; -1212,-132 -1109,-229 ; -1104,-232 -1089,-228 -974,-316 ; -987,-332 -941,-305 -882,-251 -879,-244 -879,-234 -881,-231 -887,-230 -894,-230 ; -956,-330 -909,-367 ; -952,-323 -904,-361 -752,-223 -743,-219 -729,-224 -650,-138 -647,-143 -618,-117 -598,-113 ; -880,-245 -880,-237 -882,-233 -887,-231 -894,-230 ; -746,-227 -731,-232 ; -724,-228 -659,-155 ; -656,-158 -650,-149 ; -894,-230 -968,-268 -976,-270 -983,-268 -987,-261 -986,-255 -982,-247 -971,-239 -876,-174 -868,-165 -865,-158 -867,-153 -869,-149 -873,-147 -880,-147 -890,-150 -1018,-220 -1028,-221 -1036,-216 -1041,-212 -1044,-205 -1043,-199 -1039,-191 -1017,-166 -989,-139 -950,-105 -907,-77 -868,-59 -819,-51 -862,-90 -845,-90 -816,-85 -811,-81 -828,-91 -844,-96 -860,-102 -883,-107 -918,-107 -925,-118 -938,-126 -953,-133 -971,-143 -993,-173 -1011,-188 -1022,-203 -1018,-207 -988,-197 -940,-169 -904,-149 -880,-143 -874,-145 -870,-156 -881,-172 -949,-219 -987,-251 -988,-263 -984,-268 -961,-264 -944,-253 -901,-233 -894,-230 ; -903,-372 -744,-227 -903,-372
  text "M  B  A  R  I" at -1270,-60 h55
  text "Copyright 2003 MBARI" at -1240,-500 h45
  text "1002131-MVCPowerR2" at -1235,-583.32 h45
  text "2003-DEC-29" at -1235,-663.32 h45
  text "Made in U.S.A." at -1235,-733.32 h45
  text "ADUM" at 2980,-1850 h45 r270
  text "ADUM" at 3020,-2270 h45 r90
  text "Spare" at 2420,-2450 h45
  text ".GTO" at 12740,-6040 h90
Bottom Overlay:
  text ".GBO" at 12750,-6040 h90
Top Solder:
  text ".GTS" at 12740,-6040 h90
Bottom Solder:
  text ".GBS" at 12740,-6040 h90
Drill Guide:
  text ".GG1" at 9950,-6040 h90
Mechanical 4:
  circle w10: c0,0 r5500
  circle w10: c-0.27,0 r4550.27
  lines w10: -5500,-5500 -5500,5500 5500,5500 5500,-5500 -5500,-5500
Mechanical 16:
  lines w5: -6300,-3700 -6100,-3700 ; -6300,-1300 -6100,-1300 ; -6300,1100 -6100,1100 ; -6300,3500 -6100,3500 ; -6300,5900 -6100,5900 ; -3900,-6300 -3900,-6100 ; -3900,8100 -3900,8300 ; -1500,-6300 -1500,-6100 ; -1500,8100 -1500,8300 ; 900,-6300 900,-6100 ; 900,8100 900,8300 ; 3300,-6300 3300,-6100 ; 3300,8100 3300,8300 ; 5600,-6100 13100,-6100 ; 5700,-6300 5700,-6100 ; 5700,8100 5700,8300 ; 7200,-5500 13100,-5500 ; 8100,-6300 8100,-6100 ; 8100,8100 8100,8300 ; 8600,-5800 13100,-5800 ; 8600,-5200 10100,-5200 ; 10100,-6100 10100,-5500 10100,-4900 ; 10500,-6300 10500,-6100 ; 10500,8100 10500,8300 ; 12200,-6100 12200,-5500 ; 13100,-4900 10100,-4900 ; 13100,-3700 13300,-3700 ; 13100,-1300 13300,-1300 ; 13100,1100 13300,1100 ; 13100,3500 13300,3500 ; 13100,5900 13300,5900 ; 8600,-4900 8600,-6100 7200,-6100 7200,-4900 8600,-4900 ; 8600,-4900 10100,-4900 ; 13100,-6100 13100,8100 -6100,8100 -6100,-6100 13100,-6100 ; -6300,-6300 13300,-6300 13300,8300 -6300,8300 -6300,-6300
  lines w10: 7533,-5054 7565,-5056 7596,-5074 7697,-5165 7710,-5161 7717,-5162 7831,-5249 ; 7588,-5072 7691,-5169 ; 7696,-5172 7711,-5168 7826,-5256 ; 7813,-5272 7859,-5245 7918,-5191 7921,-5184 7921,-5174 7919,-5171 7913,-5170 7906,-5170 ; 7844,-5270 7891,-5307 ; 7848,-5263 7896,-5301 8048,-5163 8057,-5159 8071,-5164 8150,-5078 8153,-5083 8182,-5057 8202,-5053 ; 7920,-5185 7920,-5177 7918,-5173 7913,-5171 7906,-5170 ; 8054,-5167 8069,-5172 ; 8076,-5168 8141,-5095 ; 8144,-5098 8150,-5089 ; 7906,-5170 7832,-5208 7824,-5210 7817,-5208 7813,-5201 7814,-5195 7818,-5187 7829,-5179 7924,-5114 7932,-5105 7935,-5098 7933,-5093 7931,-5089 7927,-5087 7920,-5087 7910,-5090 7782,-5160 7772,-5161 7764,-5156 7759,-5152 7756,-5145 7757,-5139 7761,-5131 7783,-5106 7811,-5079 7850,-5045 7893,-5017 7932,-4999 7981,-4991 7938,-5030 7955,-5030 7984,-5025 7989,-5021 7972,-5031 7956,-5036 7940,-5042 7917,-5047 7882,-5047 7875,-5058 7862,-5066 7847,-5073 7829,-5083 7807,-5113 7789,-5128 7778,-5143 7782,-5147 7812,-5137 7860,-5109 7896,-5089 7920,-5083 7926,-5085 7930,-5096 7919,-5112 7851,-5159 7813,-5191 7812,-5203 7816,-5208 7839,-5204 7856,-5193 7899,-5173 7906,-5170 ; 7897,-5312 8056,-5167 7897,-5312
  text "7" at 9370,8170 h70
  text "8" at 11740,8170 h70
  text "1" at -4980,8160 h70
  text "2" at -2700,8160 h70
  text "3" at -340,8160 h70
  text "4" at 2010,8160 h70
  text "5" at 4470,8160 h70
  text "6" at 6840,8160 h70
  text "A" at -6230,7040 h70
  text "A" at 13170,7040 h70
  text "B" at -6240,4630 h70
  text "B" at 13160,4630 h70
  text "C" at -6220,2360 h70
  text "C" at 13180,2360 h70
  text "D" at -6240,-90 h70
  text "D" at 13160,-90 h70
  text "E" at -6220,-2600 h70
  text "E" at 13180,-2600 h70
  text "M  B  A  R  I" at 7530,-5000 h55
  text "ENGINEER:" at 8650,-5000 h45
  text "TITLE:" at 10150,-5000 h45
  text "Mark Sibenac" at 9160,-5030 h70
  text "F" at -6240,-5050 h70
  text "F" at 13160,-5050 h70
  text "Main Power Distribution" at 10500,-5120 h90
  text "1 831 775 2028" at 9150,-5170 h60
  text "PCB DESIGNER:" at 8650,-5295 h45
  text "Mark Sibenac" at 9160,-5330 h70
  text "MVC - Mapping AUV" at 10520,-5340 h90
  text "Copyright      2003" at 7380,-5350 h60
  text "Monterey Bay Aquarium Research Institute" at 7250,-5460 h45
  text "1 831 775 2028" at 9150,-5470 h60
  text "DATE:" at 8650,-5600 h45
  text "PART NO.:" at 10150,-5600 h45
  text "REV:" at 12250,-5600 h45
  text ".PRINT_DATE" at 8700,-5720 h70
  text "2" at 12530,-5720 h90
  text "MVCPOWR2" at 10510,-5730 h60
  text "M.B.A.R.I." at 7280,-5740 h100
  text "7700 Sandholdt Rd." at 7270,-5840 h60
  text "FILE NAME:" at 8650,-5900 h45
  text "DWG NO:" at 10150,-5900 h45
  text "GERBER:" at 12250,-5900 h45
  text "Moss Landing, CA 95039" at 7270,-5950 h60
  text "1002131-PCB" at 10510,-5990 h60
  text ".PCB_FILE_NAME_NO_PATH" at 8700,-6020 h70
  text ".GM16" at 12360,-6030 h70
  text "Fax: 1 831 775 1646" at 7270,-6050 h60
  text "7" at 9370,-6230 h70
  text "8" at 11740,-6230 h70
  text "1" at -4980,-6240 h70
  text "2" at -2700,-6240 h70
  text "3" at -340,-6240 h70
  text "4" at 2010,-6240 h70
  text "5" at 4470,-6240 h70
  text "6" at 6840,-6240 h70
Drill Drawing:
  text ".LEGEND" at 4445,-4630 h60
  text "Drill Drawing." at 4425,-4720 h60
  text ".GD1" at 9945,-6040 h90

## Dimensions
3990,-3890 to 3700,-3700 on Mechanical 4
-3890,-4040 to -3700,-3700 on Mechanical 4
3890,-3890 to 3890,3890 on Mechanical 4
-3890,-3890 to 3890,-3890 on Mechanical 4
-5375,-5375 to -5500,-5500 on Mechanical 4
-5375,-5375 to -5500,-5500 on Mechanical 4
-5500,5500 to -5500,-5500 on Mechanical 4
-5500,-5500 to 5500,-5500 on Mechanical 4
